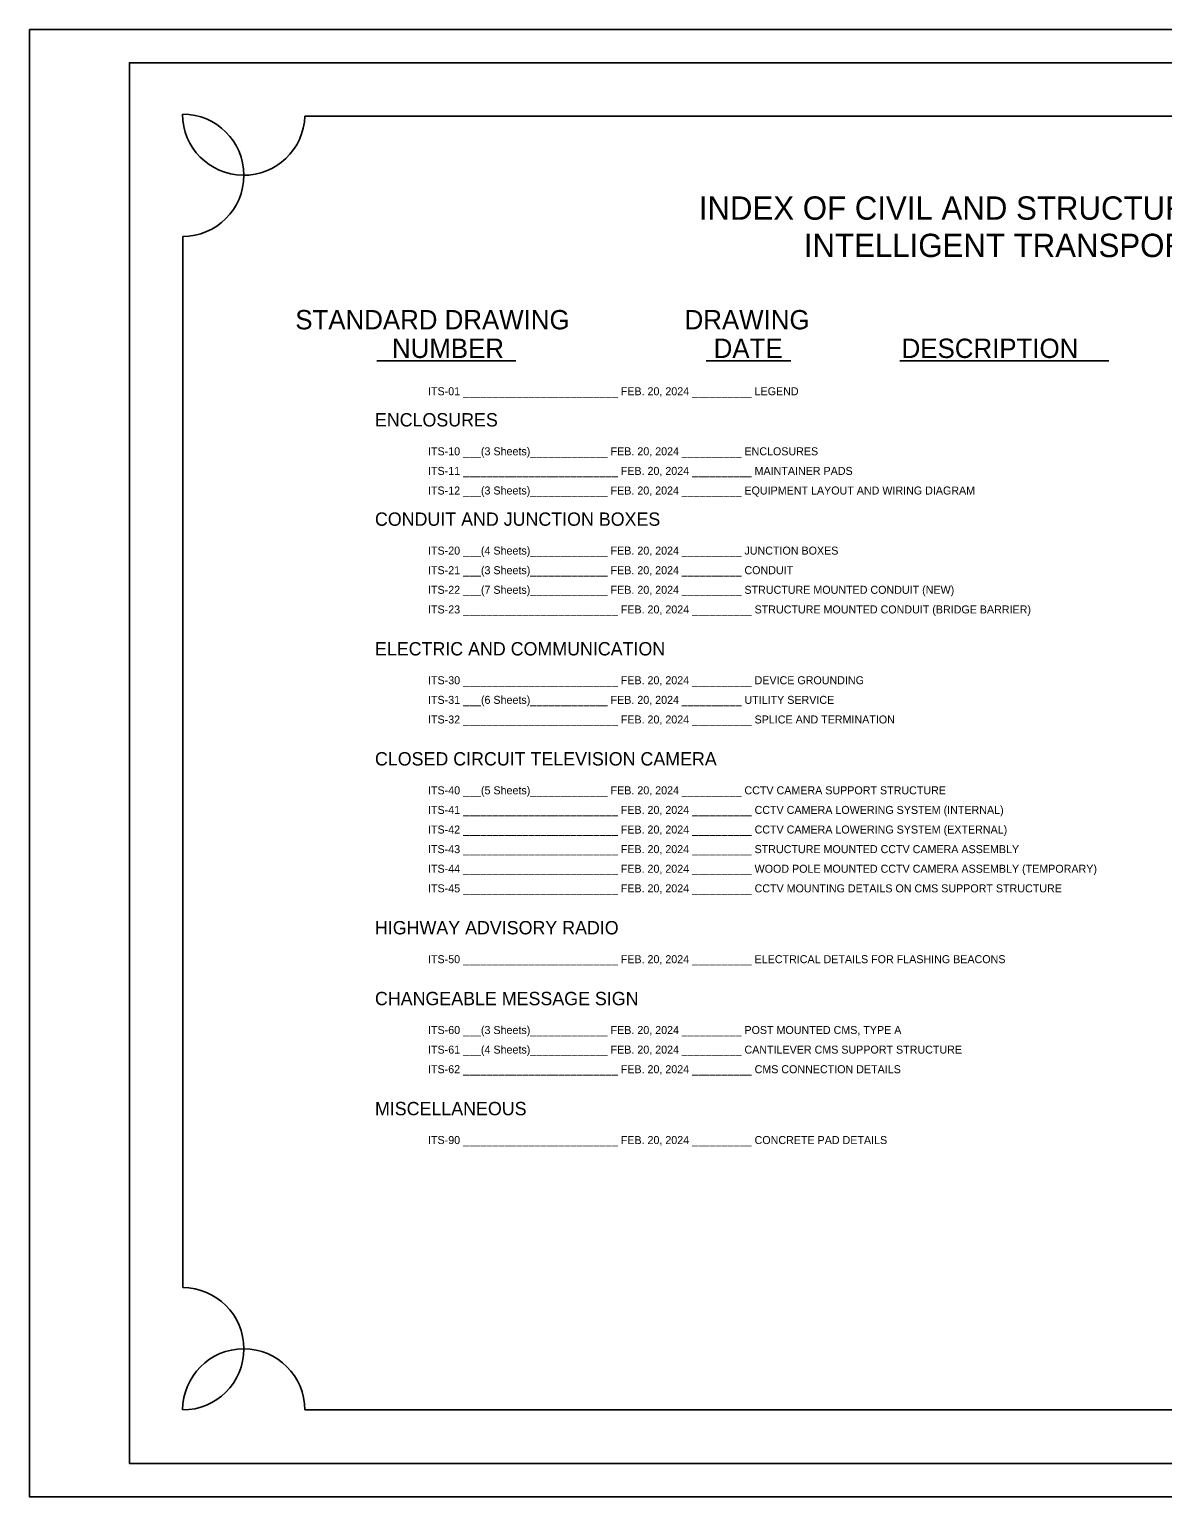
# Model space of a CAD drawing. Extents: x 2558463 to 2558497, y 334216.1 to 334238.1.
# Drawn here: x 2558462.99 to 2558479.99, y 334216.06 to 334238.06 of the extents above; entities that cross this region are included whole.
import ezdxf

# ---------------------------------------------------------------- set-up
doc = ezdxf.new("R2010")
doc.units = 0
for name, color, linetype in [('Default', 7, 'Continuous'), ('DIM TXT', 7, 'Continuous'), ('GS_plotshape_p', 7, 'Continuous'), ('Level 1', 7, 'Continuous'), ('Level 2', 7, 'Continuous')]:
    doc.layers.add(name, color=color, linetype=linetype)

msp = doc.modelspace()

# ---------------------------------------------------------------- linework, layer by layer
at = {"layer": 'Default'}
msp.add_line((2558465.294, 334219.198), (2558465.294, 334234.96), dxfattribs=at)
msp.add_lwpolyline([(2558467.127, 334217.364), (2558493.86, 334217.364)], dxfattribs=at)
at = {"layer": 'DIM TXT'}
for p, q in [((2558468.206, 334233.093), (2558470.291, 334233.093)), ((2558473.148, 334233.093), (2558474.418, 334233.093)), ((2558476.052, 334233.093), (2558479.184, 334233.093))]:
    msp.add_line(p, q, dxfattribs=at)
at = {"layer": 'GS_plotshape_p'}
msp.add_lwpolyline([(2558462.994, 334238.064), (2558496.994, 334238.064), (2558496.994, 334216.064), (2558462.994, 334216.064)], close=True, dxfattribs=at)
at = {"layer": 'Level 1'}
msp.add_lwpolyline([(2558496.494, 334216.564), (2558464.494, 334216.564), (2558464.494, 334237.564), (2558496.494, 334237.564)], close=True, dxfattribs=at)
at = {"layer": 'Level 2'}
msp.add_lwpolyline([(2558493.86, 334236.764), (2558467.127, 334236.764)], dxfattribs=at)
for centre, start, end in [((2558465.294, 334235.876), 270, 90), ((2558466.21, 334236.793), 180, 358.2117), ((2558465.294, 334218.281), 270, 90), ((2558466.21, 334217.364), 0, 180)]:
    msp.add_arc(centre, 0.917, start, end, dxfattribs=at)

# ---------------------------------------------------------------- texts
at = {"layer": 'Default'}
msp.add_text('DESCRIPTION', height=0.29, dxfattribs=at).set_placement((2558476.078, 334233.137))
at = {"layer": 'DIM TXT'}
for s, height, p in [('STANDARD DRAWING', 0.29, (2558466.983, 334233.566)), ('DRAWING', 0.29, (2558472.823, 334233.566)), ('NUMBER', 0.29, (2558468.433, 334233.137)), ('DATE', 0.29, (2558473.259, 334233.137)), ('ITS-01 __________________________ FEB. 20, 2024 __________ LEGEND', 0.12, (2558468.974, 334232.578)), ('ENCLOSURES', 0.2, (2558468.178, 334232.11)), ('ITS-10 ___(3 Sheets)_____________ FEB. 20, 2024 __________ ENCLOSURES', 0.12, (2558468.974, 334231.678)), ('ITS-11 __________________________ FEB. 20, 2024 __________ MAINTAINER PADS', 0.12, (2558468.974, 334231.384)), ('ITS-12 ___(3 Sheets)_____________ FEB. 20, 2024 __________ EQUIPMENT LAYOUT AND WIRING DIAGRAM', 0.12, (2558468.974, 334231.09)), ('CONDUIT AND JUNCTION BOXES', 0.2, (2558468.178, 334230.621)), ('ITS-20 ___(4 Sheets)_____________ FEB. 20, 2024 __________ JUNCTION BOXES', 0.12, (2558468.974, 334230.189)), ('ITS-21 ___(3 Sheets)_____________ FEB. 20, 2024 __________ CONDUIT', 0.12, (2558468.974, 334229.895)), ('ITS-22 ___(7 Sheets)_____________ FEB. 20, 2024 __________ STRUCTURE MOUNTED CONDUIT (NEW)', 0.12, (2558468.974, 334229.601)), ('ITS-23 __________________________ FEB. 20, 2024 __________ STRUCTURE MOUNTED CONDUIT (BRIDGE BARRIER)', 0.12, (2558468.974, 334229.307)), ('ELECTRIC AND COMMUNICATION', 0.2, (2558468.178, 334228.677)), ('ITS-30 __________________________ FEB. 20, 2024 __________ DEVICE GROUNDING', 0.12, (2558468.974, 334228.245)), ('ITS-31 ___(6 Sheets)_____________ FEB. 20, 2024 __________ UTILITY SERVICE', 0.12, (2558468.974, 334227.951)), ('ITS-32 __________________________ FEB. 20, 2024 __________ SPLICE AND TERMINATION', 0.12, (2558468.974, 334227.657)), ('CLOSED CIRCUIT TELEVISION CAMERA', 0.2, (2558468.178, 334227.027)), ('ITS-40 ___(5 Sheets)_____________ FEB. 20, 2024 __________ CCTV CAMERA SUPPORT STRUCTURE', 0.12, (2558468.974, 334226.595)), ('ITS-41 __________________________ FEB. 20, 2024 __________ CCTV CAMERA LOWERING SYSTEM (INTERNAL)', 0.12, (2558468.974, 334226.301)), ('ITS-42 __________________________ FEB. 20, 2024 __________ CCTV CAMERA LOWERING SYSTEM (EXTERNAL)', 0.12, (2558468.974, 334226.007)), ('ITS-43 __________________________ FEB. 20, 2024 __________ STRUCTURE MOUNTED CCTV CAMERA ASSEMBLY', 0.12, (2558468.974, 334225.713)), ('ITS-44 __________________________ FEB. 20, 2024 __________ WOOD POLE MOUNTED CCTV CAMERA ASSEMBLY (TEMPORARY)', 0.12, (2558468.974, 334225.419)), ('ITS-45 __________________________ FEB. 20, 2024 __________ CCTV MOUNTING DETAILS ON CMS SUPPORT STRUCTURE', 0.12, (2558468.974, 334225.125)), ('HIGHWAY ADVISORY RADIO', 0.2, (2558468.178, 334224.495)), ('ITS-50 __________________________ FEB. 20, 2024 __________ ELECTRICAL DETAILS FOR FLASHING BEACONS', 0.12, (2558468.974, 334224.063)), ('CHANGEABLE MESSAGE SIGN', 0.2, (2558468.178, 334223.433)), ('ITS-60 ___(3 Sheets)_____________ FEB. 20, 2024 __________ POST MOUNTED CMS, TYPE A', 0.12, (2558468.974, 334223.001)), ('ITS-61 ___(4 Sheets)_____________ FEB. 20, 2024 __________ CANTILEVER CMS SUPPORT STRUCTURE', 0.12, (2558468.974, 334222.707)), ('ITS-62 __________________________ FEB. 20, 2024 __________ CMS CONNECTION DETAILS', 0.12, (2558468.974, 334222.413)), ('MISCELLANEOUS', 0.2, (2558468.178, 334221.783)), ('ITS-90 __________________________ FEB. 20, 2024 __________ CONCRETE PAD DETAILS', 0.12, (2558468.974, 334221.351))]:
    msp.add_text(s, height=height, dxfattribs=at).set_placement(p)
at = {"layer": 'Level 2'}
for s, p in [('INDEX OF CIVIL AND STRUCTURAL STANDARDS FOR', (2558473.035, 334235.21)), ('INTELLIGENT TRANSPORTATION SYSTEMS', (2558474.611, 334234.65))]:
    msp.add_text(s, height=0.35, dxfattribs=at).set_placement(p)

doc.saveas('drawing.dxf')
